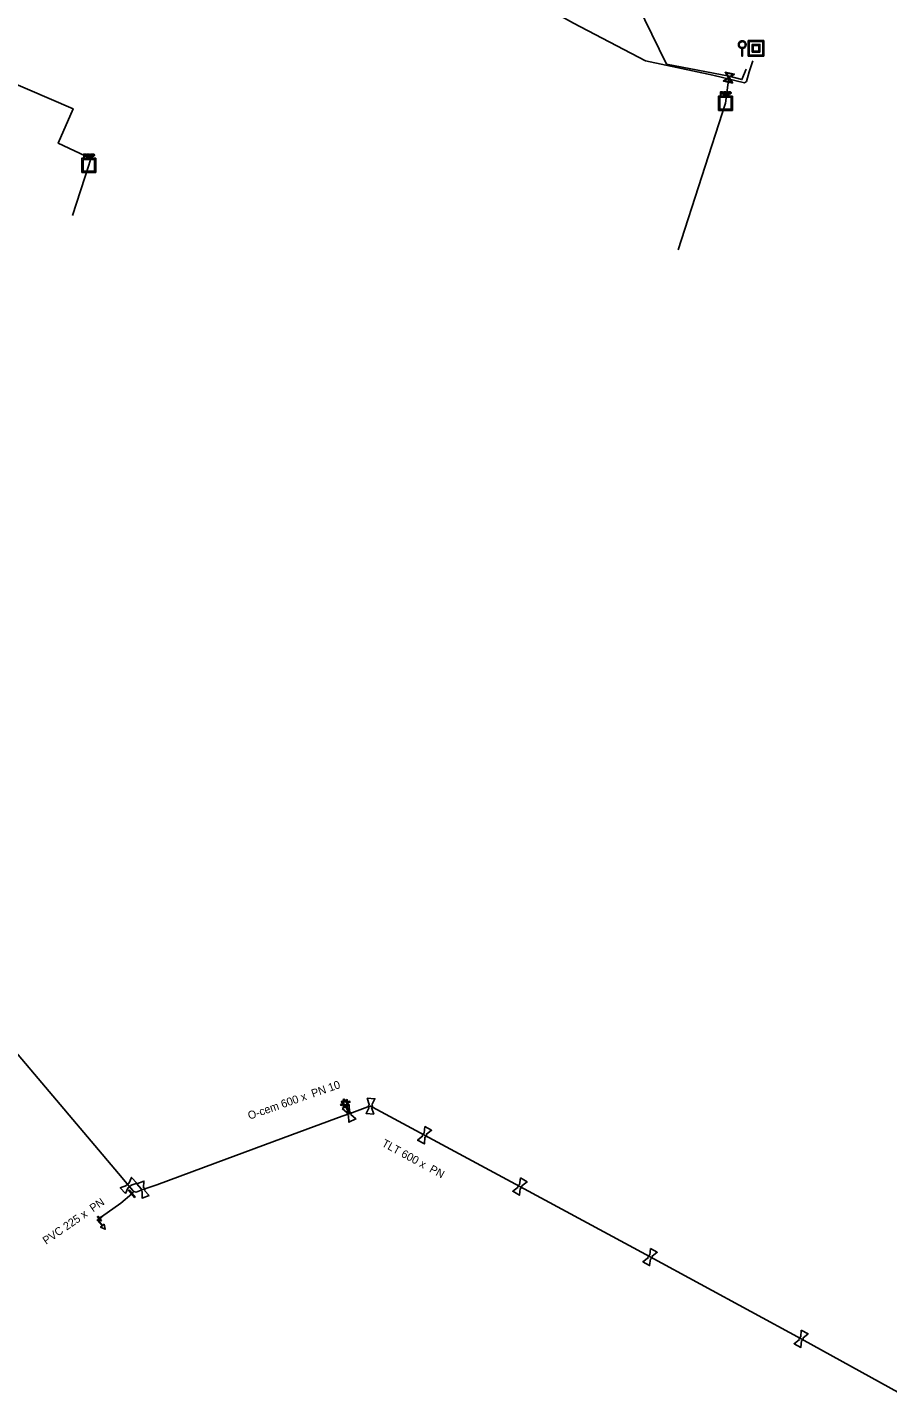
# Model space of a CAD drawing. Extents: x -643842 to -636370, y -1119190 to -1110210.
# Drawn here: x -640782.9 to -640643.2, y -1115243 to -1115021.1 of the extents above; entities that cross this region are included whole.
import ezdxf

# ---------------------------------------------------------------- set-up
doc = ezdxf.new("R2010")
doc.units = 0
for name, color, linetype in [('14', 7, 'Continuous'), ('2', 7, 'Continuous'), ('Default', 7, 'Continuous'), ('Level 16', 7, 'Continuous'), ('Level 18', 7, 'Continuous'), ('Level 20', 7, 'Continuous'), ('Level 21', 7, 'Continuous'), ('Level 23', 7, 'Continuous'), ('Level 26', 7, 'Continuous'), ('Level 28', 7, 'Continuous'), ('Level 33', 7, 'Continuous')]:
    doc.layers.add(name, color=color, linetype=linetype)

msp = doc.modelspace()

# ---------------------------------------------------------------- linework, layer by layer
at = {"layer": '14'}
for points in [[(-640665.81, -1115025.76), (-640665.81, -1115023.26), (-640663.31, -1115023.26), (-640663.31, -1115025.76), (-640665.81, -1115025.76)], [(-640663.46, -1115025.6), (-640663.46, -1115023.41), (-640665.65, -1115023.41), (-640665.65, -1115025.6), (-640663.46, -1115025.6)], [(-640665.18, -1115025.13), (-640665.18, -1115023.88), (-640663.93, -1115023.88), (-640663.93, -1115025.13), (-640665.18, -1115025.13)], [(-640664.09, -1115024.97), (-640664.09, -1115024.04), (-640665.03, -1115024.04), (-640665.03, -1115024.97), (-640664.09, -1115024.97)]]:
    msp.add_lwpolyline(points, dxfattribs=at)
at = {"layer": '2'}
msp.add_lwpolyline([(-640731.38, -1115195.7), (-640731.57, -1115195.19), (-640731.43, -1115195.14), (-640731.24, -1115195.64), (-640731.04, -1115195.21), (-640730.9, -1115195.28), (-640731.1, -1115195.7), (-640730.56, -1115195.5), (-640730.5, -1115195.65), (-640731.05, -1115195.85), (-640730.62, -1115196.05), (-640730.68, -1115196.19), (-640731.11, -1115196), (-640730.55, -1115197.48), (-640730.7, -1115197.54), (-640731.25, -1115196.05), (-640731.45, -1115196.48), (-640731.59, -1115196.41), (-640731.4, -1115195.98), (-640731.94, -1115196.18), (-640732, -1115196.04), (-640731.46, -1115195.84), (-640731.88, -1115195.64), (-640731.82, -1115195.5), (-640731.38, -1115195.7)], dxfattribs=at)
at = {"layer": 'Default'}
for points in [[(-640666.87, -1115024.53), (-640666.99, -1115024.51), (-640667.1, -1115024.45), (-640667.25, -1115024.37), (-640667.33, -1115024.22), (-640667.42, -1115024.07), (-640667.42, -1115023.91), (-640667.42, -1115023.74), (-640667.33, -1115023.59), (-640667.25, -1115023.44), (-640667.1, -1115023.36), (-640666.95, -1115023.28), (-640666.79, -1115023.28), (-640666.63, -1115023.28), (-640666.48, -1115023.36), (-640666.33, -1115023.44), (-640666.25, -1115023.59), (-640666.17, -1115023.74), (-640666.17, -1115023.91), (-640666.17, -1115024.07), (-640666.25, -1115024.22), (-640666.33, -1115024.37), (-640666.48, -1115024.45), (-640666.6, -1115024.52), (-640666.73, -1115024.53)], [(-640667.03, -1115023.48), (-640667.15, -1115023.54), (-640667.22, -1115023.66), (-640667.28, -1115023.78), (-640667.28, -1115023.91), (-640667.28, -1115024.04), (-640667.22, -1115024.15), (-640667.15, -1115024.27), (-640667.04, -1115024.34), (-640666.92, -1115024.4), (-640666.79, -1115024.4), (-640666.66, -1115024.4), (-640666.55, -1115024.34), (-640666.43, -1115024.27), (-640666.36, -1115024.15), (-640666.3, -1115024.04), (-640666.3, -1115023.91), (-640666.3, -1115023.78), (-640666.37, -1115023.66), (-640666.43, -1115023.54), (-640666.55, -1115023.48), (-640666.67, -1115023.42), (-640666.79, -1115023.42), (-640666.92, -1115023.42), (-640667.03, -1115023.48)], [(-640670.12, -1115031.58), (-640670.06, -1115031.58), (-640670.03, -1115031.58), (-640669.99, -1115031.59), (-640669.96, -1115031.61), (-640669.93, -1115031.63), (-640669.91, -1115031.67), (-640669.9, -1115031.7), (-640669.9, -1115031.74), (-640669.9, -1115031.82), (-640669.94, -1115031.87), (-640669.99, -1115031.92), (-640670.11, -1115031.92)], [(-640670.11, -1115031.85), (-640670.04, -1115031.85), (-640670.01, -1115031.82), (-640669.97, -1115031.8), (-640669.97, -1115031.75), (-640669.97, -1115031.71), (-640669.99, -1115031.69), (-640670.01, -1115031.66), (-640670.04, -1115031.65), (-640670.06, -1115031.65), (-640670.11, -1115031.65)], [(-640669.49, -1115032.03), (-640669.52, -1115031.98), (-640669.54, -1115031.95), (-640669.56, -1115031.93), (-640669.58, -1115031.91), (-640669.6, -1115031.9), (-640669.62, -1115031.9), (-640669.63, -1115031.9), (-640669.66, -1115031.9)], [(-640669.58, -1115031.83), (-640669.53, -1115031.83), (-640669.5, -1115031.82), (-640669.47, -1115031.81), (-640669.46, -1115031.79), (-640669.44, -1115031.76), (-640669.44, -1115031.73), (-640669.44, -1115031.7), (-640669.47, -1115031.67), (-640669.5, -1115031.64), (-640669.56, -1115031.64)], [(-640669.57, -1115031.58), (-640669.49, -1115031.58), (-640669.45, -1115031.59), (-640669.41, -1115031.61), (-640669.39, -1115031.65), (-640669.36, -1115031.69), (-640669.36, -1115031.73), (-640669.36, -1115031.8), (-640669.4, -1115031.84), (-640669.44, -1115031.88), (-640669.52, -1115031.89), (-640669.49, -1115031.91), (-640669.48, -1115031.92), (-640669.45, -1115031.95), (-640669.42, -1115032)], [(-640668.83, -1115031.58), (-640668.78, -1115031.58), (-640668.75, -1115031.59), (-640668.71, -1115031.59), (-640668.68, -1115031.61), (-640668.65, -1115031.63), (-640668.63, -1115031.67), (-640668.61, -1115031.7), (-640668.61, -1115031.75), (-640668.61, -1115031.82), (-640668.66, -1115031.87), (-640668.71, -1115031.92), (-640668.83, -1115031.92)], [(-640668.83, -1115031.85), (-640668.75, -1115031.85), (-640668.72, -1115031.83), (-640668.69, -1115031.8), (-640668.69, -1115031.75), (-640668.69, -1115031.71), (-640668.71, -1115031.69), (-640668.73, -1115031.66), (-640668.76, -1115031.65), (-640668.78, -1115031.65), (-640668.83, -1115031.65)], [(-640773.5, -1115041.67), (-640773.44, -1115041.67), (-640773.41, -1115041.67), (-640773.37, -1115041.68), (-640773.34, -1115041.7), (-640773.31, -1115041.72), (-640773.29, -1115041.75), (-640773.28, -1115041.79), (-640773.28, -1115041.83), (-640773.28, -1115041.91), (-640773.32, -1115041.96), (-640773.37, -1115042.01), (-640773.49, -1115042.01)], [(-640773.49, -1115041.94), (-640773.42, -1115041.94), (-640773.39, -1115041.91), (-640773.36, -1115041.89), (-640773.36, -1115041.83), (-640773.36, -1115041.8), (-640773.37, -1115041.77), (-640773.39, -1115041.75), (-640773.42, -1115041.74), (-640773.44, -1115041.74), (-640773.49, -1115041.74)], [(-640772.87, -1115042.12), (-640772.9, -1115042.07), (-640772.92, -1115042.04), (-640772.94, -1115042.01), (-640772.96, -1115042), (-640772.98, -1115041.99), (-640773, -1115041.99), (-640773.01, -1115041.99), (-640773.04, -1115041.99)], [(-640772.96, -1115041.92), (-640772.91, -1115041.92), (-640772.88, -1115041.91), (-640772.85, -1115041.9), (-640772.84, -1115041.88), (-640772.82, -1115041.85), (-640772.82, -1115041.82), (-640772.82, -1115041.78), (-640772.85, -1115041.76), (-640772.88, -1115041.73), (-640772.95, -1115041.73)], [(-640772.95, -1115041.67), (-640772.87, -1115041.67), (-640772.83, -1115041.68), (-640772.79, -1115041.7), (-640772.77, -1115041.74), (-640772.74, -1115041.78), (-640772.74, -1115041.82), (-640772.74, -1115041.89), (-640772.78, -1115041.93), (-640772.82, -1115041.97), (-640772.9, -1115041.98), (-640772.88, -1115041.99), (-640772.86, -1115042.01), (-640772.83, -1115042.04), (-640772.8, -1115042.08)], [(-640772.22, -1115041.67), (-640772.16, -1115041.67), (-640772.13, -1115041.67), (-640772.09, -1115041.68), (-640772.06, -1115041.7), (-640772.03, -1115041.72), (-640772.01, -1115041.76), (-640771.99, -1115041.79), (-640771.99, -1115041.83), (-640771.99, -1115041.91), (-640772.04, -1115041.96), (-640772.09, -1115042.01), (-640772.21, -1115042.01)], [(-640772.21, -1115041.94), (-640772.13, -1115041.94), (-640772.1, -1115041.91), (-640772.07, -1115041.89), (-640772.07, -1115041.84), (-640772.07, -1115041.8), (-640772.09, -1115041.78), (-640772.11, -1115041.75), (-640772.14, -1115041.74), (-640772.16, -1115041.74), (-640772.21, -1115041.74)], [(-640727.38, -1115196.5), (-640727.42, -1115196.46), (-640727.44, -1115196.42), (-640727.48, -1115196.34), (-640727.47, -1115196.26), (-640727.47, -1115196.18), (-640727.42, -1115196.1), (-640727.39, -1115196.06), (-640727.35, -1115196.03)], [(-640726.94, -1115196.06), (-640726.9, -1115196.09), (-640726.88, -1115196.14), (-640726.84, -1115196.22), (-640726.85, -1115196.3), (-640726.85, -1115196.38), (-640726.9, -1115196.45), (-640726.93, -1115196.5), (-640726.97, -1115196.53)], [(-640730.71, -1115197.81), (-640730.76, -1115197.8), (-640730.81, -1115197.77), (-640730.88, -1115197.72), (-640730.91, -1115197.65), (-640730.95, -1115197.57), (-640730.94, -1115197.49), (-640730.94, -1115197.43), (-640730.92, -1115197.38)], [(-640730.55, -1115197.21), (-640730.5, -1115197.22), (-640730.45, -1115197.25), (-640730.38, -1115197.3), (-640730.35, -1115197.37), (-640730.31, -1115197.45), (-640730.32, -1115197.53), (-640730.32, -1115197.59), (-640730.34, -1115197.63)], [(-640718.67, -1115201.12), (-640718.69, -1115201.08), (-640718.69, -1115201.02), (-640718.69, -1115200.94), (-640718.66, -1115200.86), (-640718.62, -1115200.79), (-640718.54, -1115200.74), (-640718.5, -1115200.72), (-640718.45, -1115200.7)], [(-640718.09, -1115200.9), (-640718.07, -1115200.94), (-640718.07, -1115201), (-640718.07, -1115201.08), (-640718.1, -1115201.16), (-640718.14, -1115201.23), (-640718.21, -1115201.27), (-640718.26, -1115201.3), (-640718.31, -1115201.31)], [(-640766.76, -1115209.19), (-640766.77, -1115209.14), (-640766.75, -1115209.09), (-640766.72, -1115209.01), (-640766.66, -1115208.95), (-640766.6, -1115208.9), (-640766.52, -1115208.88), (-640766.47, -1115208.86), (-640766.42, -1115208.87)], [(-640766.14, -1115209.17), (-640766.14, -1115209.22), (-640766.15, -1115209.27), (-640766.18, -1115209.35), (-640766.24, -1115209.41), (-640766.3, -1115209.46), (-640766.38, -1115209.48), (-640766.43, -1115209.5), (-640766.48, -1115209.49)], [(-640764.21, -1115210.13), (-640764.26, -1115210.12), (-640764.3, -1115210.08), (-640764.36, -1115210.02), (-640764.39, -1115209.95), (-640764.42, -1115209.87), (-640764.41, -1115209.79), (-640764.4, -1115209.73), (-640764.37, -1115209.69)], [(-640763.99, -1115209.55), (-640763.94, -1115209.57), (-640763.9, -1115209.6), (-640763.84, -1115209.66), (-640763.81, -1115209.73), (-640763.78, -1115209.81), (-640763.79, -1115209.89), (-640763.8, -1115209.95), (-640763.83, -1115209.99)], [(-640703.19, -1115209.45), (-640703.21, -1115209.4), (-640703.21, -1115209.35), (-640703.21, -1115209.27), (-640703.17, -1115209.19), (-640703.13, -1115209.12), (-640703.06, -1115209.08), (-640703.01, -1115209.05), (-640702.96, -1115209.04)], [(-640702.6, -1115209.25), (-640702.59, -1115209.29), (-640702.59, -1115209.35), (-640702.59, -1115209.43), (-640702.63, -1115209.51), (-640702.67, -1115209.58), (-640702.74, -1115209.62), (-640702.79, -1115209.65), (-640702.84, -1115209.66)], [(-640682.04, -1115220.88), (-640682.06, -1115220.83), (-640682.06, -1115220.78), (-640682.06, -1115220.7), (-640682.02, -1115220.62), (-640681.98, -1115220.55), (-640681.91, -1115220.51), (-640681.86, -1115220.48), (-640681.81, -1115220.47)], [(-640681.45, -1115220.68), (-640681.44, -1115220.72), (-640681.44, -1115220.78), (-640681.44, -1115220.86), (-640681.48, -1115220.94), (-640681.52, -1115221.01), (-640681.59, -1115221.05), (-640681.64, -1115221.08), (-640681.69, -1115221.09)], [(-640657.52, -1115234.18), (-640657.54, -1115234.13), (-640657.54, -1115234.08), (-640657.54, -1115234), (-640657.51, -1115233.92), (-640657.47, -1115233.85), (-640657.39, -1115233.8), (-640657.35, -1115233.78), (-640657.3, -1115233.76)], [(-640656.94, -1115233.96), (-640656.92, -1115234), (-640656.92, -1115234.06), (-640656.92, -1115234.14), (-640656.95, -1115234.22), (-640656.99, -1115234.29), (-640657.06, -1115234.33), (-640657.11, -1115234.36), (-640657.16, -1115234.37)]]:
    msp.add_open_spline(points, degree=3, dxfattribs=at)
at = {"layer": 'Level 16'}
for points in [[(-640669.54, -1115028.37), (-640668.07, -1115028.68), (-640668.09, -1115028.74), (-640668.2, -1115028.81), (-640668.9, -1115029.27), (-640668.36, -1115030.08), (-640668.38, -1115030.15), (-640669.85, -1115029.84), (-640669.83, -1115029.78), (-640669.02, -1115029.25), (-640669.48, -1115028.55), (-640669.56, -1115028.44), (-640669.54, -1115028.37)], [(-640668.51, -1115030.02), (-640668.97, -1115029.32), (-640669.67, -1115029.78), (-640668.51, -1115030.02)], [(-640669.41, -1115028.5), (-640668.95, -1115029.2), (-640668.25, -1115028.74), (-640669.41, -1115028.5)], [(-640766.34, -1115209.9), (-640765.38, -1115211.06), (-640765.46, -1115211.12), (-640766.42, -1115209.96), (-640766.34, -1115209.9)]]:
    msp.add_lwpolyline(points, dxfattribs=at)
at = {"layer": 'Level 18'}
for points in [[(-640668.38, -1115032.25), (-640668.38, -1115034.58), (-640670.64, -1115034.58), (-640670.64, -1115032.25), (-640668.38, -1115032.25)], [(-640670.45, -1115032.45), (-640670.45, -1115034.38), (-640668.57, -1115034.38), (-640668.57, -1115032.45), (-640670.45, -1115032.45)], [(-640670.33, -1115032.15), (-640670.33, -1115031.58), (-640670.12, -1115031.58)], [(-640670.11, -1115031.92), (-640670.26, -1115031.92), (-640670.26, -1115032.15), (-640670.33, -1115032.15)], [(-640670.11, -1115031.65), (-640670.26, -1115031.65), (-640670.26, -1115031.85)], [(-640670.26, -1115031.85), (-640670.11, -1115031.85)], [(-640669.82, -1115032.15), (-640669.82, -1115031.58), (-640669.57, -1115031.58)], [(-640669.66, -1115031.9), (-640669.74, -1115031.9), (-640669.74, -1115032.15), (-640669.82, -1115032.15)], [(-640669.56, -1115031.64), (-640669.74, -1115031.64), (-640669.74, -1115031.83)], [(-640669.74, -1115031.83), (-640669.58, -1115031.83)], [(-640669.42, -1115032), (-640669.32, -1115032.15), (-640669.41, -1115032.15), (-640669.49, -1115032.03)], [(-640669.24, -1115032.15), (-640669.24, -1115031.58), (-640669.16, -1115031.58), (-640669.16, -1115032.15), (-640669.24, -1115032.15)], [(-640669.05, -1115032.15), (-640669.05, -1115031.58), (-640668.83, -1115031.58)], [(-640668.83, -1115031.92), (-640668.97, -1115031.92), (-640668.97, -1115032.15), (-640669.05, -1115032.15)], [(-640668.83, -1115031.65), (-640668.97, -1115031.65), (-640668.97, -1115031.85)], [(-640668.97, -1115031.85), (-640668.83, -1115031.85)], [(-640771.76, -1115042.34), (-640771.76, -1115044.66), (-640774.02, -1115044.66), (-640774.02, -1115042.34), (-640771.76, -1115042.34)], [(-640773.83, -1115042.54), (-640773.83, -1115044.47), (-640771.95, -1115044.47), (-640771.95, -1115042.54), (-640773.83, -1115042.54)], [(-640773.71, -1115042.24), (-640773.71, -1115041.67), (-640773.5, -1115041.67)], [(-640773.49, -1115042.01), (-640773.64, -1115042.01), (-640773.64, -1115042.24), (-640773.71, -1115042.24)], [(-640773.49, -1115041.74), (-640773.64, -1115041.74), (-640773.64, -1115041.94)], [(-640773.64, -1115041.94), (-640773.49, -1115041.94)], [(-640773.2, -1115042.24), (-640773.2, -1115041.67), (-640772.95, -1115041.67)], [(-640773.04, -1115041.99), (-640773.13, -1115041.99), (-640773.13, -1115042.24), (-640773.2, -1115042.24)], [(-640772.95, -1115041.73), (-640773.13, -1115041.73), (-640773.13, -1115041.92)], [(-640773.13, -1115041.92), (-640772.96, -1115041.92)], [(-640772.8, -1115042.08), (-640772.7, -1115042.24), (-640772.79, -1115042.24), (-640772.87, -1115042.12)], [(-640772.62, -1115042.24), (-640772.62, -1115041.67), (-640772.55, -1115041.67), (-640772.55, -1115042.24), (-640772.62, -1115042.24)], [(-640772.43, -1115042.24), (-640772.43, -1115041.67), (-640772.22, -1115041.67)], [(-640772.21, -1115042.01), (-640772.36, -1115042.01), (-640772.36, -1115042.24), (-640772.43, -1115042.24)], [(-640772.21, -1115041.74), (-640772.36, -1115041.74), (-640772.36, -1115041.94)], [(-640772.36, -1115041.94), (-640772.21, -1115041.94)]]:
    msp.add_lwpolyline(points, dxfattribs=at)
at = {"layer": 'Level 21'}
for points in [[(-640665.07, -1115026.55), (-640665.67, -1115028.33), (-640666.08, -1115029.88), (-640666.41, -1115030.11), (-640671.57, -1115028.86), (-640682.52, -1115026.52), (-640694.21, -1115020.4), (-640704.92, -1115014.42), (-640718.12, -1115009.98), (-640734.15, -1115004.95), (-640751.68, -1114999.51), (-640768.91, -1114993.97)], [(-640691.15, -1115001.29), (-640690.88, -1115002.89), (-640679.07, -1115027.07), (-640668.93, -1115029.02), (-640666.84, -1115029.58), (-640666.15, -1115027.91)], [(-640730.63, -1115197.51), (-640731.74, -1115197.9), (-640739.81, -1115200.89), (-640752.4, -1115205.55), (-640761.86, -1115209.04), (-640764.1, -1115209.84), (-640765.2, -1115210.24), (-640765.57, -1115210.17), (-640765.63, -1115210.12), (-640765.77, -1115209.98), (-640766.45, -1115209.18), (-640767.5, -1115207.95), (-640797.45, -1115172.52)], [(-640730.63, -1115197.51), (-640727.59, -1115196.38), (-640727.16, -1115196.28), (-640726.81, -1115196.43), (-640718.38, -1115201.01), (-640702.9, -1115209.35), (-640681.75, -1115220.78), (-640657.23, -1115234.07), (-640641.03, -1115242.98)], [(-640765.63, -1115210.12), (-640765.76, -1115210.31), (-640765.9, -1115210.51), (-640767.71, -1115212.07), (-640770.86, -1115214.25)]]:
    msp.add_lwpolyline(points, dxfattribs=at)
at = {"layer": 'Level 23'}
for points in [[(-640803.09, -1115023.34), (-640803.02, -1115023.35), (-640801.27, -1115023.22), (-640775.45, -1115034.33), (-640777.86, -1115039.92), (-640772.54, -1115042.42), (-640772.89, -1115043.5), (-640775.54, -1115051.64)], [(-640668.93, -1115029.02), (-640668.96, -1115029.26), (-640669.51, -1115033.41), (-640677.17, -1115057.21)]]:
    msp.add_lwpolyline(points, dxfattribs=at)
at = {"layer": 'Level 26'}
msp.add_lwpolyline([(-640666.73, -1115024.53), (-640666.73, -1115025.78), (-640666.87, -1115025.78), (-640666.87, -1115024.53)], dxfattribs=at)
at = {"layer": 'Level 28'}
for points in [[(-640731.74, -1115196.66), (-640730.61, -1115196.11), (-640730.55, -1115197.21)], [(-640730.92, -1115197.38), (-640731.74, -1115196.66)], [(-640726.97, -1115196.53), (-640726.63, -1115197.57), (-640727.87, -1115197.48), (-640727.38, -1115196.5)], [(-640727.69, -1115194.99), (-640726.45, -1115195.08), (-640726.94, -1115196.06)], [(-640727.35, -1115196.03), (-640727.69, -1115194.99)], [(-640730.34, -1115197.63), (-640729.52, -1115198.36), (-640730.65, -1115198.91), (-640730.71, -1115197.81)], [(-640718.31, -1115201.31), (-640718.41, -1115202.41), (-640719.52, -1115201.82), (-640718.67, -1115201.12)], [(-640718.45, -1115200.7), (-640718.35, -1115199.61)], [(-640718.35, -1115199.61), (-640717.24, -1115200.2), (-640718.09, -1115200.9)], [(-640766.42, -1115208.87), (-640765.97, -1115207.87), (-640765.11, -1115208.78), (-640766.14, -1115209.17)], [(-640702.96, -1115209.04), (-640702.82, -1115207.95)], [(-640702.82, -1115207.95), (-640701.74, -1115208.58), (-640702.6, -1115209.25)], [(-640766.93, -1115210.49), (-640767.79, -1115209.58), (-640766.76, -1115209.19)], [(-640766.48, -1115209.49), (-640766.93, -1115210.49)], [(-640764.37, -1115209.69), (-640765.12, -1115208.88), (-640763.95, -1115208.45), (-640763.99, -1115209.55)], [(-640763.08, -1115210.8), (-640764.25, -1115211.23), (-640764.21, -1115210.13)], [(-640763.83, -1115209.99), (-640763.08, -1115210.8)], [(-640702.84, -1115209.66), (-640702.98, -1115210.75), (-640704.06, -1115210.12), (-640703.19, -1115209.45)], [(-640681.69, -1115221.09), (-640681.83, -1115222.18), (-640682.91, -1115221.55), (-640682.04, -1115220.88)], [(-640681.81, -1115220.47), (-640681.67, -1115219.38)], [(-640681.67, -1115219.38), (-640680.59, -1115220.01), (-640681.45, -1115220.68)], [(-640657.16, -1115234.37), (-640657.26, -1115235.47), (-640658.37, -1115234.88), (-640657.52, -1115234.18)], [(-640657.3, -1115233.76), (-640657.2, -1115232.67)], [(-640657.2, -1115232.67), (-640656.09, -1115233.26), (-640656.94, -1115233.96)]]:
    msp.add_lwpolyline(points, dxfattribs=at)
at = {"layer": 'Level 33'}
msp.add_lwpolyline([(-640771.18, -1115214.64), (-640771.37, -1115214.8), (-640770.65, -1115215.66), (-640770.42, -1115215.46), (-640770.23, -1115216.28), (-640770.99, -1115215.94), (-640770.75, -1115215.74), (-640771.55, -1115214.78), (-640771.26, -1115214.54), (-640771.5, -1115214.26), (-640771.4, -1115214.18), (-640771.17, -1115214.46), (-640770.88, -1115214.23), (-640770.8, -1115214.32), (-640771.09, -1115214.56), (-640770.85, -1115214.84), (-640770.94, -1115214.92), (-640771.18, -1115214.64)], dxfattribs=at)

# ---------------------------------------------------------------- texts
at = {"layer": 'Level 20'}
for s, rotation, p in [('O-cem 600 x  PN 10', 19.2448, (-640746.81, -1115198.5)), ('TLT 600 x  PN ', 331.4849, (-640725.44, -1115202.71)), ('PVC 225 x  PN ', 34.6857, (-640779.83, -1115218.82))]:
    msp.add_text(s, height=1.3, rotation=rotation, dxfattribs=at).set_placement(p)

doc.saveas('drawing.dxf')
